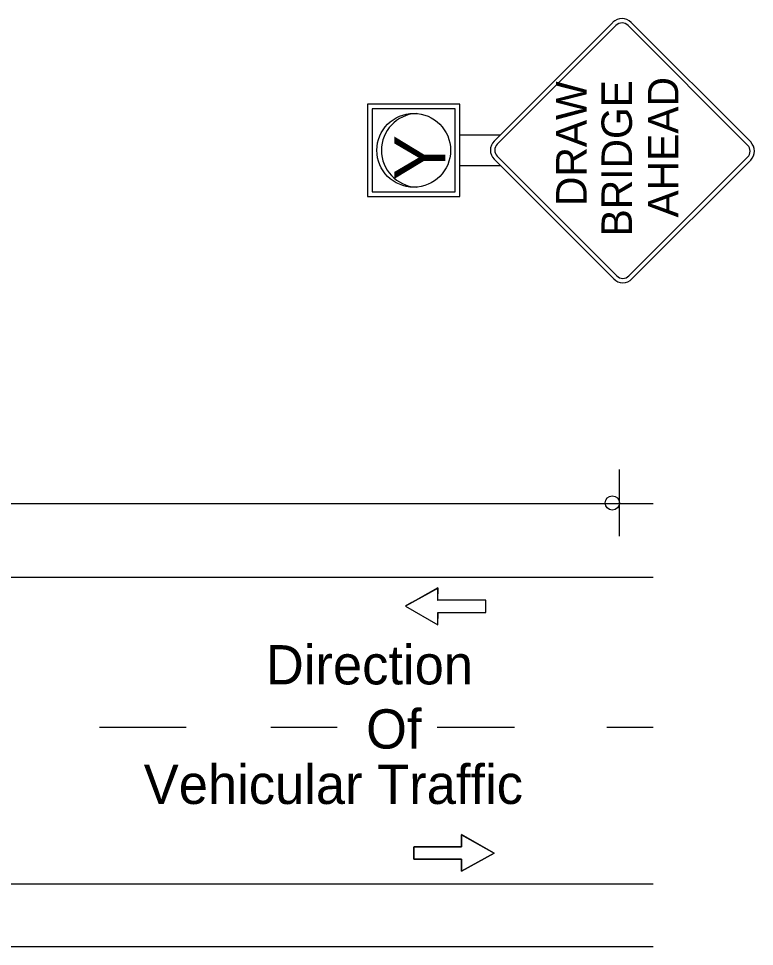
# Model space of a CAD drawing. Extents: x 15 to 764, y 7 to 487.
# Drawn here: x 310.3 to 375.9, y 393.2 to 475.8 of the extents above; entities that cross this region are included whole.
import ezdxf

# ---------------------------------------------------------------- set-up
doc = ezdxf.new("R2010")
doc.units = 0
doc.layers.add('Default', color=7, linetype='Continuous')
doc.layers.add('TextStructures', color=7, linetype='Continuous')

msp = doc.modelspace()

# ---------------------------------------------------------------- linework, layer by layer
at = {"layer": 'Default'}
for p, q in [((363.264, 475.506), (352.679, 464.928)), ((375.547, 464.844), (364.889, 475.506)), ((363.537, 475.233), (352.953, 464.654)), ((375.273, 464.569), (364.615, 475.233)), ((349.614, 468.213), (341.393, 468.213)), ((341.393, 468.213), (341.393, 459.992)), ((349.614, 459.992), (349.614, 468.213)), ((349.203, 467.801), (341.804, 467.801)), ((341.804, 467.801), (341.804, 460.403)), ((349.203, 460.403), (349.203, 467.801)), ((353.192, 465.442), (349.624, 465.442)), ((363.337, 452.638), (352.678, 463.302)), ((363.61, 452.912), (352.952, 463.576)), ((375.273, 463.49), (364.688, 452.912)), ((375.547, 463.217), (364.962, 452.638)), ((353.254, 462.725), (349.624, 462.725)), ((341.393, 459.992), (349.614, 459.992)), ((341.804, 460.403), (349.203, 460.403)), ((363.844, 429.706), (363.844, 435.651)), ((22.063, 432.626), (366.864, 432.626)), ((22.063, 426.064), (366.864, 426.064)), ((347.67, 425.092), (344.756, 423.469)), ((347.666, 425.09), (345.348, 423.799)), ((347.666, 424.002), (347.67, 425.092)), ((344.756, 423.469), (347.658, 421.826)), ((351.925, 424.005), (347.666, 424.002)), ((351.931, 422.913), (351.925, 424.005)), ((347.658, 421.826), (347.662, 422.915)), ((347.658, 421.826), (347.662, 422.915)), ((347.662, 422.915), (351.931, 422.913)), ((347.662, 422.915), (347.683, 422.915)), ((317.497, 412.687), (325.216, 412.687)), ((332.755, 412.687), (338.686, 412.687)), ((347.605, 412.687), (354.487, 412.687)), ((362.727, 412.687), (366.864, 412.687)), ((349.766, 403.118), (349.762, 402.028)), ((352.668, 401.475), (349.766, 403.118)), ((349.762, 402.028), (345.503, 402.022)), ((345.503, 402.022), (345.51, 400.934)), ((349.754, 399.852), (352.668, 401.475)), ((349.754, 399.852), (352.668, 401.475)), ((345.51, 400.934), (349.758, 400.934)), ((345.51, 400.934), (349.758, 400.934)), ((349.758, 400.934), (349.754, 399.852)), ((349.758, 400.934), (349.754, 399.852)), ((22.063, 398.745), (366.864, 398.745)), ((22.063, 393.153), (366.864, 393.153)), ((272.458, 393.153), (366.864, 393.153))]:
    msp.add_line(p, q, dxfattribs=at)
for points in [[(351.921, 424.014), (347.666, 423.98), (347.666, 425.109), (344.761, 423.467), (347.658, 421.826), (347.683, 422.915), (351.931, 422.919)], [(345.503, 402.014), (349.767, 402.035), (349.767, 403.112), (352.668, 401.475), (349.754, 399.862), (349.758, 400.917), (345.51, 400.934)]]:
    msp.add_lwpolyline(points, close=True, dxfattribs=at)
for points in [[(347.683, 422.915), (351.931, 422.919), (351.921, 424.014), (347.666, 423.98), (347.666, 425.09)], [(345.348, 423.799), (344.761, 423.467), (347.658, 421.826)], [(352.668, 401.475), (349.767, 403.112), (349.767, 402.035), (345.503, 402.014), (345.51, 400.934)]]:
    msp.add_lwpolyline(points, dxfattribs=at)
for centre, radius in [((345.503, 464.102), 3.288), ((363.207, 432.678), 0.637)]:
    msp.add_circle(centre, radius, dxfattribs=at)
for centre, radius, start, end in [((364.076, 474.695), 1.15, 44.98483, 134.9852), ((364.076, 474.695), 0.762, 44.98483, 134.9852), ((345.914, 464.102), 3.288, 93.58332, 266.41668), ((353.491, 464.115), 1.15, 134.98524, 224.9843), ((374.733, 464.031), 1.15, 314.98573, 44.98455), ((353.491, 464.115), 0.762, 134.98524, 224.9843), ((374.733, 464.031), 0.762, 314.98573, 44.98455), ((364.149, 453.452), 1.15, 224.98473, 314.98571), ((364.149, 453.452), 0.762, 224.98473, 314.98571)]:
    msp.add_arc(centre, radius, start, end, dxfattribs=at)

# ---------------------------------------------------------------- texts
for s, height, p in [('DRAW', 2.7176, (360.915, 459.138)), ('BRIDGE', 2.7176, (364.962, 456.426)), ('AHEAD', 2.7176, (369.1, 458.114)), ('Y', 4.536, (348.309, 461.422))]:
    msp.add_text(s, height=height, rotation=90, dxfattribs=at).set_placement(p)
at = {"layer": 'TextStructures'}
for s, p in [('Direction', (332.321, 416.504)), ('Of', (341.257, 410.786)), ('Vehicular Traffic', (321.429, 405.851))]:
    msp.add_text(s, height=3.5, dxfattribs=at).set_placement(p)

doc.saveas('drawing.dxf')
